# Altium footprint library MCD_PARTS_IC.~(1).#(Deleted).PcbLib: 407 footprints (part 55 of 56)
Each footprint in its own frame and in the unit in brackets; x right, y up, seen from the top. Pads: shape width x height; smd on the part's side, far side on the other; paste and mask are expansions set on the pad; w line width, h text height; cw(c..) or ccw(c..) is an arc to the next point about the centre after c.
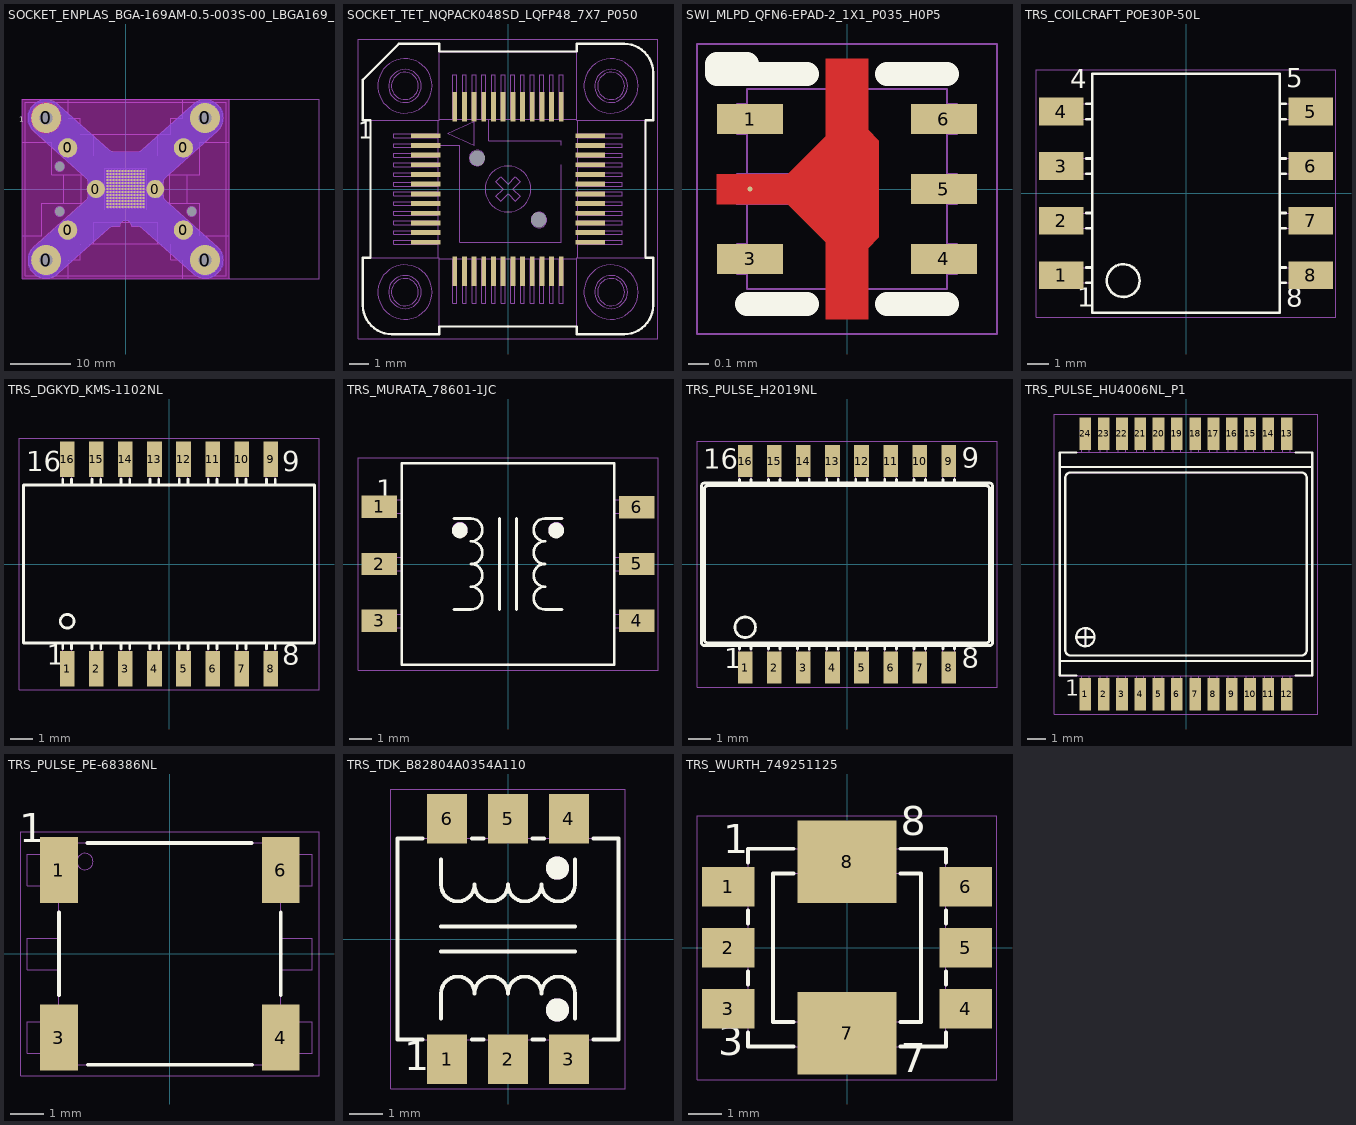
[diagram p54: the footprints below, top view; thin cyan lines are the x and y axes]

## SOCKET_ENPLAS_BGA-169AM-0.5-003S-00_LBGA169_P050_3D-OPEN [mm] "MCD-02114"
height 41
pads (182):
  round 5 hole 2.15 mask+0.05: 0(-13.25,-11.85) 0(-13.25,11.85) 0(13.25,-11.85) 0(13.25,11.85)
  round 0 hole 1.6 unplated mask+0.05: 0(-11,-3.75) 0(-11,3.75) 0(11,-3.75)
  round 3.2 smd paste-2 mask+0.05: 0(-9.65,-6.85) 0(-9.65,6.85) 0(9.65,-6.85) 0(9.65,6.85)
  round 3 smd paste-2 mask+0.05: 0(-4.945,0) 0(4.945,0)
  rrect30% 0.35x0.35 smd paste-0.2 mask+0.05: A1(-3,3) A2(-2.5,3) A3(-2,3) A4(-1.5,3) A5(-1,3) A6(-0.5,3) A7(0,3) A8(0.5,3) A9(1,3) A10(1.5,3) A11(2,3) A12(2.5,3) A13(3,3) B1(-3,2.5) B2(-2.5,2.5) B3(-2,2.5) B4(-1.5,2.5) B5(-1,2.5) B6(-0.5,2.5) B7(0,2.5) B8(0.5,2.5) B9(1,2.5) B10(1.5,2.5) B11(2,2.5) B12(2.5,2.5) B13(3,2.5) C1(-3,2) C2(-2.5,2) C3(-2,2) C4(-1.5,2) C5(-1,2) C6(-0.5,2) C7(0,2) C8(0.5,2) C9(1,2) C10(1.5,2) C11(2,2) C12(2.5,2) C13(3,2) D1(-3,1.5) D2(-2.5,1.5) D3(-2,1.5) D4(-1.5,1.5) D5(-1,1.5) D6(-0.5,1.5) D7(0,1.5) D8(0.5,1.5) D9(1,1.5) D10(1.5,1.5) D11(2,1.5) D12(2.5,1.5) D13(3,1.5) E1(-3,1) E2(-2.5,1) E3(-2,1) E4(-1.5,1) E5(-1,1) E6(-0.5,1) E7(0,1) E8(0.5,1) E9(1,1) E10(1.5,1) E11(2,1) E12(2.5,1) E13(3,1) F1(-3,0.5) F2(-2.5,0.5) F3(-2,0.5) F4(-1.5,0.5) F5(-1,0.5) F6(-0.5,0.5) F7(0,0.5) F8(0.5,0.5) F9(1,0.5) F10(1.5,0.5) F11(2,0.5) F12(2.5,0.5) F13(3,0.5) G1(-3,0) G2(-2.5,0) G3(-2,0) G4(-1.5,0) G5(-1,0) G6(-0.5,0) G7(0,0) G8(0.5,0) G9(1,0) G10(1.5,0) G11(2,0) G12(2.5,0) G13(3,0) H1(-3,-0.5) H2(-2.5,-0.5) H3(-2,-0.5) H4(-1.5,-0.5) H5(-1,-0.5) H6(-0.5,-0.5) H7(0,-0.5) H8(0.5,-0.5) H9(1,-0.5) H10(1.5,-0.5) H11(2,-0.5) H12(2.5,-0.5) H13(3,-0.5) J1(-3,-1) J2(-2.5,-1) J3(-2,-1) J4(-1.5,-1) J5(-1,-1) J6(-0.5,-1) J7(0,-1) J8(0.5,-1) J9(1,-1) J10(1.5,-1) J11(2,-1) J12(2.5,-1) J13(3,-1) K1(-3,-1.5) K2(-2.5,-1.5) K3(-2,-1.5) K4(-1.5,-1.5) K5(-1,-1.5) K6(-0.5,-1.5) K7(0,-1.5) K8(0.5,-1.5) K9(1,-1.5) K10(1.5,-1.5) K11(2,-1.5) K12(2.5,-1.5) K13(3,-1.5) L1(-3,-2) L2(-2.5,-2) L3(-2,-2) L4(-1.5,-2) L5(-1,-2) L6(-0.5,-2) L7(0,-2) L8(0.5,-2) L9(1,-2) L10(1.5,-2) L11(2,-2) L12(2.5,-2) L13(3,-2) M1(-3,-2.5) M2(-2.5,-2.5) M3(-2,-2.5) M4(-1.5,-2.5) M5(-1,-2.5) M6(-0.5,-2.5) M7(0,-2.5) M8(0.5,-2.5) M9(1,-2.5) M10(1.5,-2.5) M11(2,-2.5) M12(2.5,-2.5) M13(3,-2.5) N1(-3,-3) N2(-2.5,-3) N3(-2,-3) N4(-1.5,-3) N5(-1,-3) N6(-0.5,-3) N7(0,-3) N8(0.5,-3) N9(1,-3) N10(1.5,-3) N11(2,-3) N12(2.5,-3) N13(3,-3)
Top Layer:
  circle w0.01: c-13.25,11.85 r1.075
  circle w0.01: c-13.25,11.85 r2.5
Top Layer keep-out:
  region: 4.975,15 4.975,1.5 4.95,1.5 4.803,1.493 4.515,1.435 4.243,1.323 3.998,1.16 3.79,0.952 3.627,0.707 3.515,0.435 3.457,0.147 3.45,0 3.457,-0.147 3.515,-0.435 3.627,-0.707 3.79,-0.952 3.998,-1.16 4.243,-1.323 4.515,-1.435 4.803,-1.493 4.95,-1.5 4.975,-1.5 4.975,-15 0,-15 0,-3.375 3.375,-3.375 3.375,3.375 -3.375,3.375 -3.375,-3.375 0,-3.375 0,-15 -4.95,-15 -4.95,-1.5 -4.803,-1.493 -4.515,-1.435 -4.243,-1.323 -3.998,-1.16 -3.79,-0.952 -3.627,-0.707 -3.515,-0.435 -3.457,-0.147 -3.45,0 -3.457,0.147 -3.515,0.435 -3.627,0.707 -3.79,0.952 -3.998,1.16 -4.243,1.323 -4.515,1.435 -4.803,1.493 -4.95,1.5 -4.95,15
  region: 9.675,15 4.975,15 4.975,1.5 5.122,1.493 5.41,1.435 5.682,1.323 5.927,1.16 6.135,0.952 6.298,0.707 6.41,0.435 6.468,0.147 6.475,0 6.468,-0.147 6.41,-0.435 6.298,-0.707 6.135,-0.952 5.927,-1.16 5.682,-1.323 5.41,-1.435 5.122,-1.493 4.975,-1.5 4.975,-15 9.675,-15 9.675,-8.45 9.518,-8.442 9.211,-8.381 8.921,-8.261 8.66,-8.087 8.438,-7.865 8.264,-7.604 8.144,-7.314 8.083,-7.007 8.075,-6.85 8.083,-6.693 8.144,-6.386 8.264,-6.096 8.438,-5.835 8.66,-5.613 8.921,-5.439 9.211,-5.319 9.518,-5.258 9.675,-5.25 9.675,-4.9 11.025,-4.9 11.025,-4.55 10.947,-4.546 10.793,-4.516 10.648,-4.456 10.517,-4.368 10.407,-4.258 10.319,-4.127 10.259,-3.982 10.229,-3.828 10.225,-3.75 10.229,-3.672 10.259,-3.518 10.319,-3.373 10.407,-3.242 10.517,-3.132 10.648,-3.044 10.793,-2.984 10.947,-2.954 11.025,-2.95 11.025,4.925 9.675,4.925 9.675,5.25 9.518,5.258 9.211,5.319 8.921,5.439 8.66,5.613 8.438,5.835 8.264,6.096 8.144,6.386 8.083,6.693 8.075,6.85 8.083,7.007 8.144,7.314 8.264,7.604 8.438,7.865 8.66,8.087 8.921,8.261 9.211,8.381 9.518,8.442 9.675,8.45
  region: -9.65,15 -4.95,15 -4.95,1.5 -5.097,1.493 -5.385,1.435 -5.657,1.323 -5.902,1.16 -6.11,0.952 -6.273,0.707 -6.385,0.435 -6.443,0.147 -6.45,0 -6.443,-0.147 -6.385,-0.435 -6.273,-0.707 -6.11,-0.952 -5.902,-1.16 -5.657,-1.323 -5.385,-1.435 -5.097,-1.493 -4.95,-1.5 -4.95,-15 -9.65,-15 -9.65,-8.45 -9.493,-8.442 -9.186,-8.381 -8.896,-8.261 -8.635,-8.087 -8.413,-7.865 -8.239,-7.604 -8.119,-7.314 -8.058,-7.007 -8.05,-6.85 -8.058,-6.693 -8.119,-6.386 -8.239,-6.096 -8.413,-5.835 -8.635,-5.613 -8.896,-5.439 -9.186,-5.319 -9.493,-5.258 -9.65,-5.25 -9.65,-4.9 -11,-4.9 -11,-4.55 -10.922,-4.546 -10.768,-4.516 -10.623,-4.456 -10.492,-4.368 -10.382,-4.258 -10.294,-4.127 -10.234,-3.982 -10.204,-3.828 -10.2,-3.75 -10.204,-3.672 -10.234,-3.518 -10.294,-3.373 -10.382,-3.242 -10.492,-3.132 -10.623,-3.044 -10.768,-2.984 -10.922,-2.954 -11,-2.95 -11,2.95 -10.922,2.954 -10.768,2.984 -10.623,3.044 -10.492,3.132 -10.382,3.242 -10.294,3.373 -10.234,3.518 -10.204,3.672 -10.2,3.75 -10.204,3.828 -10.234,3.982 -10.294,4.127 -10.382,4.258 -10.492,4.368 -10.623,4.456 -10.768,4.516 -10.922,4.546 -11,4.55 -11,4.925 -9.65,4.925 -9.65,5.25 -9.493,5.258 -9.186,5.319 -8.896,5.439 -8.635,5.613 -8.413,5.835 -8.239,6.096 -8.119,6.386 -8.058,6.693 -8.05,6.85 -8.058,7.007 -8.119,7.314 -8.239,7.604 -8.413,7.865 -8.635,8.087 -8.896,8.261 -9.186,8.381 -9.493,8.442 -9.65,8.45
  region: -17.25,15 -13.25,15 -13.25,14.347 -13.253,14.347 -13.498,14.335 -13.978,14.239 -14.43,14.052 -14.837,13.78 -15.183,13.434 -15.455,13.027 -15.642,12.575 -15.738,12.095 -15.75,11.85 -15.738,11.605 -15.642,11.125 -15.455,10.673 -15.183,10.266 -14.837,9.92 -14.43,9.648 -13.978,9.461 -13.498,9.365 -13.253,9.353 -13.25,9.353 -13.25,-9.353 -13.253,-9.353 -13.498,-9.365 -13.978,-9.461 -14.43,-9.648 -14.837,-9.92 -15.183,-10.266 -15.455,-10.673 -15.642,-11.125 -15.738,-11.605 -15.75,-11.85 -15.738,-12.095 -15.642,-12.575 -15.455,-13.027 -15.183,-13.434 -14.837,-13.78 -14.43,-14.052 -13.978,-14.239 -13.498,-14.335 -13.253,-14.347 -13.25,-14.347 -13.25,-15 -17.25,-15
  region: 17.275,15 13.275,15 13.275,14.347 13.278,14.347 13.523,14.335 14.003,14.239 14.455,14.052 14.862,13.78 15.208,13.434 15.48,13.027 15.667,12.575 15.763,12.095 15.775,11.85 15.763,11.605 15.667,11.125 15.48,10.673 15.208,10.266 14.862,9.92 14.455,9.648 14.003,9.461 13.523,9.365 13.278,9.353 13.275,9.353 13.275,-9.353 13.278,-9.353 13.523,-9.365 14.003,-9.461 14.455,-9.648 14.862,-9.92 15.208,-10.266 15.48,-10.673 15.667,-11.125 15.763,-11.605 15.775,-11.85 15.763,-12.095 15.667,-12.575 15.48,-13.027 15.208,-13.434 14.862,-13.78 14.455,-14.052 14.003,-14.239 13.523,-14.335 13.278,-14.347 13.275,-14.347 13.275,-15 17.275,-15
  region: -13.25,15 -9.65,15 -9.65,8.45 -9.807,8.442 -10.114,8.381 -10.404,8.261 -10.665,8.087 -10.887,7.865 -11.061,7.604 -11.181,7.314 -11.242,7.007 -11.25,6.85 -11.242,6.693 -11.181,6.386 -11.061,6.096 -10.887,5.835 -10.665,5.613 -10.404,5.439 -10.114,5.319 -9.807,5.258 -9.65,5.25 -9.65,4.925 -11,4.925 -11,4.55 -11.078,4.546 -11.232,4.516 -11.377,4.456 -11.508,4.368 -11.618,4.258 -11.706,4.127 -11.766,3.982 -11.796,3.828 -11.8,3.75 -11.796,3.672 -11.766,3.518 -11.706,3.373 -11.618,3.242 -11.508,3.132 -11.377,3.044 -11.232,2.984 -11.078,2.954 -11,2.95 -11,-2.95 -11.078,-2.954 -11.232,-2.984 -11.377,-3.044 -11.508,-3.132 -11.618,-3.242 -11.706,-3.373 -11.766,-3.518 -11.796,-3.672 -11.8,-3.75 -11.796,-3.828 -11.766,-3.982 -11.706,-4.127 -11.618,-4.258 -11.508,-4.368 -11.377,-4.456 -11.232,-4.516 -11.078,-4.546 -11,-4.55 -11,-4.9 -9.65,-4.9 -9.65,-5.25 -9.807,-5.258 -10.114,-5.319 -10.404,-5.439 -10.665,-5.613 -10.887,-5.835 -11.061,-6.096 -11.181,-6.386 -11.242,-6.693 -11.25,-6.85 -11.242,-7.007 -11.181,-7.314 -11.061,-7.604 -10.887,-7.865 -10.665,-8.087 -10.404,-8.261 -10.114,-8.381 -9.807,-8.442 -9.65,-8.45 -9.65,-15 -13.25,-15 -13.25,-14.347 -13.247,-14.347 -13.002,-14.335 -12.522,-14.239 -12.07,-14.052 -11.663,-13.78 -11.317,-13.434 -11.045,-13.027 -10.858,-12.575 -10.762,-12.095 -10.75,-11.85 -10.762,-11.605 -10.858,-11.125 -11.045,-10.673 -11.317,-10.266 -11.663,-9.92 -12.07,-9.648 -12.522,-9.461 -13.002,-9.365 -13.247,-9.353 -13.25,-9.353 -13.25,9.353 -13.247,9.353 -13.002,9.365 -12.522,9.461 -12.07,9.648 -11.663,9.92 -11.317,10.266 -11.045,10.673 -10.857,11.125 -10.762,11.605 -10.75,11.85 -10.762,12.095 -10.857,12.575 -11.045,13.027 -11.317,13.434 -11.663,13.78 -12.07,14.052 -12.522,14.239 -13.002,14.335 -13.247,14.347 -13.253,14.347
  region: 13.275,15 9.675,15 9.675,8.45 9.832,8.442 10.139,8.381 10.429,8.261 10.69,8.087 10.912,7.865 11.086,7.604 11.206,7.314 11.267,7.007 11.275,6.85 11.267,6.693 11.206,6.386 11.086,6.096 10.912,5.835 10.69,5.613 10.429,5.439 10.139,5.319 9.832,5.258 9.675,5.25 9.675,4.925 11.025,4.925 11.025,-2.95 11.103,-2.954 11.257,-2.984 11.402,-3.044 11.532,-3.132 11.643,-3.242 11.731,-3.373 11.791,-3.518 11.821,-3.672 11.825,-3.75 11.821,-3.828 11.791,-3.982 11.731,-4.127 11.643,-4.258 11.533,-4.368 11.402,-4.456 11.257,-4.516 11.103,-4.546 11.025,-4.55 11.025,-4.9 9.675,-4.9 9.675,-5.25 9.832,-5.258 10.139,-5.319 10.429,-5.439 10.69,-5.613 10.912,-5.835 11.086,-6.096 11.206,-6.386 11.267,-6.693 11.275,-6.85 11.267,-7.007 11.206,-7.314 11.086,-7.604 10.912,-7.865 10.69,-8.087 10.429,-8.261 10.139,-8.381 9.832,-8.442 9.675,-8.45 9.675,-15 13.275,-15 13.275,-14.347 13.03,-14.335 12.55,-14.24 12.097,-14.053 11.69,-13.781 11.343,-13.435 11.071,-13.028 10.883,-12.575 10.787,-12.095 10.775,-11.85 10.787,-11.605 10.883,-11.125 11.07,-10.673 11.342,-10.266 11.688,-9.92 12.095,-9.648 12.547,-9.461 13.027,-9.365 13.272,-9.353 13.275,9.353 13.03,9.365 12.55,9.46 12.097,9.647 11.69,9.919 11.343,10.265 11.071,10.672 10.883,11.125 10.787,11.605 10.775,11.85 10.787,12.095 10.882,12.575 11.07,13.027 11.342,13.434 11.688,13.78 12.095,14.052 12.547,14.239 13.027,14.335 13.272,14.347
Bottom Layer keep-out:
  region: 1,-6.247 2.238,-6.25 2.113,-6.1 0.997,-6.198
  region: 194 vertices and 0 holes, not listed, extent -16.275,-14.875 16.263,14.875
Top Overlay:
  text "1" at -17.775,10.85 h1.5
Bottom Overlay:
  lines w0.1: 6.542,-1.832 15.371,-9.729 cw(c13.25,-11.85) 11.129,-13.971 2.781,-6.506 ccw(c2.113,-7.25) 2.125,-6.25 1,-6.25 ccw(c0,-6.25) -1,-6.25 -2.125,-6.25 ccw(c-2.113,-7.25) -2.781,-6.506 -11.129,-13.971 cw(c-13.25,-11.85) -15.371,-9.729 -6.625,-1.906 ccw(c-7.25,-1.125) -6.25,-1.125 -6.25,1.125 ccw(c-7.25,1.125) -6.625,1.906 -15.371,9.729 cw(c-13.25,11.85) -11.129,13.971 -2.781,6.506 ccw(c-2.113,7.25) -2.125,6.25 2.125,6.25 ccw(c2.113,7.25) 2.781,6.506 11.129,13.971 cw(c13.25,11.85) 15.371,9.729 6.625,1.906 ccw(c7.25,1.125) 6.25,1.125 6.25,-1.125 ccw(c7.25,-1.125) 6.625,-1.906
Top Solder:
  rectangle: -17.25,-15 17.25,15
M14-Top Assembly:
  drawing of 1377 lines, arcs and shapes, not listed
  text "'.Designator'" at -2,3.5 h0.75
  text "A1" at -3.375,3.621 h0.8
  text "A13" at 2.375,3.621 h0.8
  text "N1" at -3.375,-4.104 h0.8
  text "N13" at 2.4,-4.129 h0.8
M15-Bottom Assembly:
  circle w0.01: c-13.25,11.85 r1.075
  circle w0.01: c-13.25,11.85 r2.5
  circle w0.01: c-13.25,-11.85 r1.075
  circle w0.01: c-13.25,-11.85 r2.5
  circle w0.01: c13.25,-11.85 r1.075
  circle w0.01: c13.25,-11.85 r2.5
  circle w0.01: c13.25,11.85 r1.075
  circle w0.01: c13.25,11.85 r2.5
  lines w0.01: 6.542,-1.832 15.371,-9.729 cw(c13.25,-11.85) 11.129,-13.971 2.781,-6.506 ccw(c2.113,-7.25) 2.125,-6.25 1,-6.25 ccw(c0,-6.25) -1,-6.25 -2.125,-6.25 ccw(c-2.113,-7.25) -2.781,-6.506 -11.129,-13.971 cw(c-13.25,-11.85) -15.371,-9.729 -6.625,-1.906 ccw(c-7.25,-1.125) -6.25,-1.125 -6.25,1.125 ccw(c-7.25,1.125) -6.625,1.906 -15.371,9.729 cw(c-13.25,11.85) -11.129,13.971 -2.781,6.506 ccw(c-2.113,7.25) -2.125,6.25 2.125,6.25 ccw(c2.113,7.25) 2.781,6.506 11.129,13.971 cw(c13.25,11.85) 15.371,9.729 6.625,1.906 ccw(c7.25,1.125) 6.25,1.125 6.25,-1.125 ccw(c7.25,-1.125) 6.625,-1.906
M16-Top Courtyard:
  lines w0.01: -10.3,-2.4 -10.3,2.4 ; -5.33,-9.1 -5.33,-5.51 5.33,-5.51 5.33,-9.1 ; -5.33,9.1 -5.33,5.51 5.33,5.51 5.33,9.1 ; 10.3,-2.4 10.3,2.4 ; -9.55,11.8 -9.55,15 ; -9.55,11.8 -9.55,15 ; -9.55,11.8 -7.55,11.8 -7.55,9.1 7.55,9.1 7.55,11.8 9.55,11.8 9.55,15 -9.55,15 ; 17.25,15 32.25,15 32.25,-15 ; 17.25,15 17.25,-15 32.25,-15 ; 17.25,15 -17.25,15 -17.25,-15 32.25,-15 ; -17.25,-7.8 -13.95,-7.8 -13.95,-2.4 -7.39,-2.4 -7.39,2.4 -12.35,2.4 -12.35,7.8 -17.25,7.8 -17.25,-7.8 ; -9.55,-15 9.55,-15 9.55,-11.8 7.55,-11.8 7.55,-9.1 -7.55,-9.1 -7.55,-11.8 -9.55,-11.8 -9.55,-15 ; 7.39,-2.4 7.39,2.4 12.35,2.4 12.35,7.8 17.25,7.8 17.25,-7.8 12.35,-7.8 12.35,-2.4 7.39,-2.4
  text "COVER KEEP OUT AREA" at 23.714,-10.75 h2
  text "(MAX HEIGHT 3.5MM)" at 27.08,-9.25 h2
  text "ZONE." at 10.112,-0.938 h0.7
  text "RESTRICTION" at 9.424,-2.063 h0.7
  text "COMP HEIGHT" at 8.812,-2.312 h0.7
  text "2.0MM MAX" at 8.083,-1.75 h0.7
  text "HEIGHT RESTRICTION ZONE." at 15.714,-6.39 h1
  text "2.5MM MAXIMUM COMPONENT" at 14.444,-6.75 h1
  text "2.5MM MAXIMUM COMPONENT" at 6.75,11.529 h1
  text "HEIGHT RESTRICTION ZONE." at 6.39,12.799 h1
  text "2.0MM MAXIMUM" at 3.75,6.646 h1
  text "COMPONENT HEIGHT" at 4.75,7.654 h1
  text "RESTRICTION ZONE." at 4.64,8.674 h1
  text "RESTRICTION ZONE." at -4.64,-8.674 h1
  text "COMPONENT HEIGHT" at -4.75,-7.654 h1
  text "2.0MM MAXIMUM" at -3.75,-6.646 h1
  text "HEIGHT RESTRICTION ZONE." at -6.39,-12.799 h1
  text "2.5MM MAXIMUM COMPONENT" at -6.75,-11.529 h1
  text "2.5MM MAXIMUM COMPONENT" at -15.154,6.75 h1
  text "HEIGHT RESTRICTION ZONE." at -16.424,6.39 h1
  text "2.0MM MAX" at -8.083,1.75 h0.7
  text "COMP HEIGHT" at -8.812,2.312 h0.7
  text "RESTRICTION" at -9.424,2.063 h0.7
  text "ZONE." at -10.111,0.938 h0.7
M17-Bottom Courtyard:
  lines w0.01: 6.542,-1.832 15.371,-9.729 cw(c13.25,-11.85) 11.129,-13.971 2.781,-6.506 ccw(c2.113,-7.25) 2.125,-6.25 1,-6.25 ccw(c0,-6.25) -1,-6.25 -2.125,-6.25 ccw(c-2.113,-7.25) -2.781,-6.506 -11.129,-13.971 cw(c-13.25,-11.85) -15.371,-9.729 -6.625,-1.906 ccw(c-7.25,-1.125) -6.25,-1.125 -6.25,1.125 ccw(c-7.25,1.125) -6.625,1.906 -15.371,9.729 cw(c-13.25,11.85) -11.129,13.971 -2.781,6.506 ccw(c-2.113,7.25) -2.125,6.25 2.125,6.25 ccw(c2.113,7.25) 2.781,6.506 11.129,13.971 cw(c13.25,11.85) 15.371,9.729 6.625,1.906 ccw(c7.25,1.125) 6.25,1.125 6.25,-1.125 ccw(c7.25,-1.125) 6.625,-1.906
3D body: height 4.4, standoff -3.6, extent 12.184,-12.923 14.325,-10.777
3D body: height 3, standoff 2, extent 10.75,-14.347 15.75,-9.353
3D body: height 4, standoff 3, extent 10.75,-11.6 13,-9.35
3D body: height 4, standoff 3, extent 13.5,-11.6 15.75,-9.35
3D body: height 4, standoff 3, extent 10.75,-14.35 13,-12.1
3D body: height 4, standoff 3, extent 13.5,-14.35 15.75,-12.1
3D body: height 4.4, standoff -3.6, extent 12.184,10.777 14.325,12.923
3D body: height 3, standoff 2, extent 10.75,9.353 15.75,14.347
3D body: height 4, standoff 3, extent 10.75,12.1 13,14.35
3D body: height 4, standoff 3, extent 13.5,12.1 15.75,14.35
3D body: height 4, standoff 3, extent 10.75,9.35 13,11.6
3D body: height 4, standoff 3, extent 13.5,9.35 15.75,11.6
3D body: height 4.4, standoff -3.6, extent -14.316,10.777 -12.175,12.923
3D body: height 3, standoff 2, extent -15.75,9.353 -10.75,14.347
3D body: height 4, standoff 3, extent -15.75,12.1 -13.5,14.35
3D body: height 4, standoff 3, extent -13,12.1 -10.75,14.35
3D body: height 4, standoff 3, extent -15.75,9.35 -13.5,11.6
3D body: height 4, standoff 3, extent -13,9.35 -10.75,11.6
3D body: height 4.4, standoff -3.6, extent -14.316,-12.923 -12.175,-10.777
3D body: height 3, standoff 2, extent -15.75,-14.347 -10.75,-9.353
3D body: height 4, standoff 3, extent -15.75,-11.6 -13.5,-9.35
3D body: height 4, standoff 3, extent -13,-11.6 -10.75,-9.35
3D body: height 4, standoff 3, extent -15.75,-14.35 -13.5,-12.1
3D body: height 4, standoff 3, extent -13,-14.35 -10.75,-12.1
3D body: height -1.6, standoff -3.6, extent -16.25,-14.875 16.262,14.875
3D body: height 41, standoff 0, extent -16.75,-14.5 16.75,14.5
3D body "5C-042-342-01_IC_SOCKET_Open_with_PCB.STEP": height 41.05, standoff -5.83, extent -17.25,-15 32.252,15

## SOCKET_TET_NQPACK048SD_LQFP48_7X7_P050 [mm] "MCD-03917"
height 9.45
pads (50):
  round 0 hole 0.8 unplated mask+0.05: 0(-1.6,1.6) 0(1.6,-1.6)
  rect 1.5x0.25 smd mask+0.05: 1(-4.25,2.75) 2(-4.25,2.25) 3(-4.25,1.75) 4(-4.25,1.25) 5(-4.25,0.75) 6(-4.25,0.25) 7(-4.25,-0.25) 8(-4.25,-0.75) 9(-4.25,-1.25) 10(-4.25,-1.75) 11(-4.25,-2.25) 12(-4.25,-2.75) 25(4.25,-2.75) 26(4.25,-2.25) 27(4.25,-1.75) 28(4.25,-1.25) 29(4.25,-0.75) 30(4.25,-0.25) 31(4.25,0.25) 32(4.25,0.75) 33(4.25,1.25) 34(4.25,1.75) 35(4.25,2.25) 36(4.25,2.75)
  rect 0.25x1.5 smd mask+0.05: 13(-2.75,-4.25) 14(-2.25,-4.25) 15(-1.75,-4.25) 16(-1.25,-4.25) 17(-0.75,-4.25) 18(-0.25,-4.25) 19(0.25,-4.25) 20(0.75,-4.25) 21(1.25,-4.25) 22(1.75,-4.25) 23(2.25,-4.25) 24(2.75,-4.25) 37(2.75,4.25) 38(2.25,4.25) 39(1.75,4.25) 40(1.25,4.25) 41(0.75,4.25) 42(0.25,4.25) 43(-0.25,4.25) 44(-0.75,4.25) 45(-1.25,4.25) 46(-1.75,4.25) 47(-2.25,4.25) 48(-2.75,4.25)
Top Overlay:
  lines w0.12: -7.5,-6 ccw(c-6,-6) -6,-7.5 -3.55,-7.5 -3.55,-7.1 3.55,-7.1 3.55,-7.5 6,-7.5 ccw(c6,-6) 7.5,-6 7.5,-3.55 7.1,-3.55 7.1,3.55 7.5,3.55 7.5,6 ccw(c6,6) 6,7.5 3.55,7.5 3.55,7.1 -3.55,7.1 -3.55,7.5 -5.638,7.5 -7.5,5.638 -7.5,3.55 -7.1,3.55 -7.1,-3.55 -7.5,-3.55 -7.5,-6
  text "1" at -7.75,2.297 h1.5
M14-Top Assembly:
  drawing of 221 lines, arcs and shapes, not listed
  text "048SD" at -2.05,-2.389 h1
  text "TET" at 0.85,1.475 h1
  text "1" at -6.55,2.325 h1.5
  text "'.Designator'" at -2,-0.5 h0.75
M16-Top Courtyard:
  lines w0.025: -7.75,-7.75 -7.75,7.75 7.75,7.75 7.75,-7.75 -7.75,-7.75
3D body: height 5.55, standoff 0, extent -5,-5 5,5
3D body: height 9.45, standoff 5.55, extent -7.5,3.55 -3.55,7.5
3D body: height 9.45, standoff 5.55, extent -7.5,-7.5 -3.55,-3.55
3D body: height 9.45, standoff 5.55, extent 3.55,-7.5 7.5,-3.55
3D body: height 9.45, standoff 5.55, extent 3.55,3.55 7.5,7.5
3D body: height 7, standoff 5.55, extent -7.1,-7.1 7.1,7.1

## SWI_MLPD_QFN6-EPAD-2_1X1_P035_H0P5 [mm] "MCD-03674"
height 0.5
pads (6):
  rect 0.33x0.15 smd mask+0.05: 1(-0.485,0.35) 3(-0.485,-0.35) 4(0.485,-0.35) 5(0.485,0) 6(0.485,0.35)
  round 0.025 smd mask+0.012: 2(-0.485,0)
Top Layer:
  region: -0.295,0.075 -0.105,0.265 -0.105,0.65 0.105,0.65 0.105,0.295 0.16,0.24 0.16,-0.24 0.105,-0.295 0.105,-0.65 -0.105,-0.65 -0.105,-0.265 -0.295,-0.075 -0.65,-0.075 -0.65,0.075
Top Overlay:
  lines w0.12: -0.5,-0.575 -0.2,-0.575 ; -0.2,0.575 -0.5,0.575 ; 0.2,-0.575 0.5,-0.575 ; 0.2,0.575 0.5,0.575 ; -0.5,0.575 -0.5,0.625 -0.65,0.625 -0.65,0.575 -0.5,0.575
Top Solder:
  rectangle: -0.7,-0.125 -0.23,0.125
M14-Top Assembly:
  lines w0.01: -0.5,-0.425 -0.55,-0.425 -0.55,-0.275 -0.5,-0.275 ; -0.5,-0.075 -0.55,-0.075 ; -0.5,0.275 -0.55,0.275 -0.55,0.425 -0.5,0.425 ; 0.5,-0.425 0.55,-0.425 0.55,-0.275 0.5,-0.275 ; 0.5,-0.075 0.55,-0.075 0.55,0.075 0.5,0.075 ; 0.5,0.275 0.55,0.275 0.55,0.425 0.5,0.425 ; -0.55,-0.075 -0.55,0.075 -0.25,0.075 -0.075,0.25 -0.075,0.55 0.075,0.55 0.075,0.275 0.13,0.22 ; -0.55,-0.075 -0.25,-0.075 -0.075,-0.25 -0.075,-0.55 0.075,-0.55 0.075,-0.275 0.13,-0.22 ; 0.13,-0.22 0.13,0.22 ; 0.13,-0.22 0.13,-0.22 ; 0.13,0.22 0.13,0.22 ; 0.13,0.22 0.13,0.22 ; -0.5,-0.5 0.5,-0.5 0.5,0.5 -0.5,0.5 -0.5,-0.5
  text "'.Designator'" at -2,-0.5 h0.75
  text "1" at -0.626,0.288 h0.2
  text "3" at -0.663,-0.411 h0.2
  text "4" at 0.57,-0.414 h0.2
  text "6" at 0.57,0.287 h0.2
  text "2" at -0.043,-0.064 h0.2
M16-Top Courtyard:
  lines w0.01: -0.75,-0.725 0.75,-0.725 0.75,0.725 -0.1,0.725 -0.75,0.725 -0.75,-0.725
3D body: height 0.51, standoff 0.5, extent -0.45,0.25 -0.25,0.45
3D body: height 0.5, standoff 0.05, extent -0.5,-0.5 0.5,0.5
3D body: height 0.18, standoff 0, extent -0.55,-0.425 -0.5,-0.275
3D body: height 0.18, standoff 0, extent -0.55,-0.075 -0.5,0.075
3D body: height 0.18, standoff 0, extent -0.55,0.275 -0.5,0.425
3D body: height 0.05, standoff 0, extent -0.5,-0.5 0.13,0.5
3D body: height 0.18, standoff 0, extent -0.075,-0.55 0.075,-0.5
3D body: height 0.18, standoff 0, extent 0.5,0.275 0.55,0.425
3D body: height 0.18, standoff 0, extent 0.5,-0.075 0.55,0.075
3D body: height 0.18, standoff 0, extent 0.5,-0.425 0.55,-0.275
3D body: height 0.18, standoff 0, extent -0.075,0.5 0.075,0.55
3D body: height 0.05, standoff 0, extent 0.325,0.275 0.55,0.425
3D body: height 0.05, standoff 0, extent 0.325,-0.075 0.55,0.075
3D body: height 0.05, standoff 0, extent 0.325,-0.425 0.55,-0.275
3D body: height 0.05, standoff 0, extent -0.55,-0.425 -0.325,-0.275
3D body: height 0.05, standoff 0, extent -0.55,0.275 -0.325,0.425

## TRS_COILCRAFT_POE30P-50L [mm]
height 9.02
pads (8):
  rect 2.03x1.27 smd mask+0.05: 1(-5.715,-3.75) 2(-5.715,-1.25) 3(-5.715,1.25) 4(-5.715,3.75) 5(5.715,3.75) 6(5.715,1.25) 7(5.715,-1.25) 8(5.715,-3.75)
Top Overlay:
  circle w0.12: c-2.875,-4 r0.752
  lines w0.12: -4.575,-4.1 -4.3,-4.1 ; -4.575,-3.4 -4.3,-3.4 ; -4.575,-1.6 -4.3,-1.6 ; -4.575,-0.9 -4.3,-0.9 ; -4.575,0.9 -4.3,0.9 ; -4.575,1.6 -4.3,1.6 ; -4.575,3.4 -4.3,3.4 ; -4.575,4.1 -4.3,4.1 ; -4.3,5.45 -4.275,5.475 4.3,5.475 4.3,-5.475 -3.375,-5.475 -4.3,-5.475 -4.3,5.475 ; 4.3,-4.1 4.575,-4.1 ; 4.3,-3.4 4.575,-3.4 ; 4.3,-1.6 4.575,-1.6 ; 4.3,-0.9 4.575,-0.9 ; 4.3,0.9 4.575,0.9 ; 4.3,1.6 4.575,1.6 ; 4.3,3.4 4.575,3.4 ; 4.3,4.1 4.575,4.1
  text "8" at 4.6,-5.5 h1.5
  text "5" at 4.6,4.575 h1.5
  text "4" at -5.3,4.525 h1.5
  text "1" at -4.975,-5.5 h1.5
M14-Top Assembly:
  circle w0.01: c-2.875,-4 r0.75
  lines w0.01: -4.3,-4.1 -6.6,-4.1 -6.6,-3.4 -4.3,-3.4 ; -4.3,-1.6 -6.6,-1.6 -6.6,-0.9 -4.3,-0.9 ; -4.3,0.9 -6.6,0.9 -6.6,1.6 -4.3,1.6 ; -4.3,3.4 -6.6,3.4 -6.6,4.1 -4.3,4.1 ; 4.3,-4.1 6.6,-4.1 6.6,-3.4 4.3,-3.4 ; 4.3,-1.6 6.6,-1.6 6.6,-0.9 4.3,-0.9 ; 4.3,0.9 6.6,0.9 6.6,1.6 4.3,1.6 ; 4.3,3.4 6.6,3.4 6.6,4.1 4.3,4.1 ; -4.3,-5.46 4.3,-5.46 4.3,5.46 -4.3,5.46 -4.3,-5.46
  text "8" at 5.5,-4.1 h1.1
  text "7" at 5.5,-1.6 h1.1
  text "6" at 5.5,0.9 h1.1
  text "5" at 5.475,3.4 h1.1
  text "4" at -5.975,3.4 h1.1
  text "3" at -5.975,0.9 h1.1
  text "2" at -5.95,-1.6 h1.1
  text "1" at -5.825,-4.1 h1.1
  text "'.Designator'" at -2,-0.5 h0.75
M16-Top Courtyard:
  lines w0.01: -6.875,-5.675 -6.875,4.225 -6.875,5.675 6.875,5.675 6.875,-5.675 -6.875,-5.675
3D body "POE30P-50L.STEP": height 9.02, standoff 0, extent -6.6,-5.46 6.6,5.46
3D body: height 9.02, standoff 0, extent -4.3,-5.45 4.3,5.45

## TRS_DGKYD_KMS-1102NL [mm]
height 6.2
pads (16):
  rect 0.64x1.55 smd mask+0.05: 1(-4.445,-4.575) 2(-3.175,-4.575) 3(-1.905,-4.575) 4(-0.635,-4.575) 5(0.635,-4.575) 6(1.905,-4.575) 7(3.175,-4.575) 8(4.445,-4.575) 9(4.445,4.575) 10(3.175,4.575) 11(1.905,4.575) 12(0.635,4.575) 13(-0.635,4.575) 14(-1.905,4.575) 15(-3.175,4.575) 16(-4.445,4.575)
Top Overlay:
  circle w0.12: c-4.445,-2.5 r0.3
  lines w0.12: -4.635,-3.7 -4.635,-3.45 ; -4.635,3.45 -4.635,3.7 ; -4.255,-3.7 -4.255,-3.45 ; -4.255,3.45 -4.255,3.7 ; -3.365,-3.7 -3.365,-3.45 ; -3.365,3.45 -3.365,3.7 ; -2.984,-3.7 -2.984,-3.45 ; -2.984,3.45 -2.984,3.7 ; -2.095,-3.7 -2.095,-3.45 ; -2.095,3.45 -2.095,3.7 ; -1.714,-3.7 -1.714,-3.45 ; -1.714,3.45 -1.714,3.7 ; -0.826,-3.7 -0.826,-3.45 ; -0.826,3.45 -0.826,3.7 ; -0.445,-3.7 -0.445,-3.45 ; -0.445,3.45 -0.445,3.7 ; 0.445,-3.7 0.445,-3.45 ; 0.445,3.45 0.445,3.7 ; 0.826,-3.7 0.826,-3.45 ; 0.826,3.45 0.826,3.7 ; 1.714,-3.7 1.714,-3.45 ; 1.714,3.45 1.714,3.7 ; 2.095,-3.7 2.095,-3.45 ; 2.095,3.45 2.095,3.7 ; 2.984,-3.7 2.984,-3.45 ; 2.984,3.45 2.984,3.7 ; 3.365,-3.7 3.365,-3.45 ; 3.365,3.45 3.365,3.7 ; 4.255,-3.7 4.255,-3.45 ; 4.255,3.45 4.255,3.7 ; 4.635,-3.7 4.635,-3.45 ; 4.635,3.45 4.635,3.7 ; -6.35,-3.45 6.35,-3.45 6.35,3.45 -6.35,3.45 -6.35,-3.45
  text "16" at -6.223,3.75 h1.5
  text "9" at 4.953,3.75 h1.5
  text "8" at 4.953,-4.7 h1.5
  text "1" at -5.334,-4.7 h1.5
M14-Top Assembly:
  lines w0.01: -4.635,-4 -4.255,-4 ; -4.635,-3.45 -4.635,-4.7 -4.255,-4.7 -4.255,-3.45 ; -4.635,3.45 -4.635,4.7 -4.255,4.7 -4.255,3.45 ; -4.635,4 -4.255,4 ; -3.365,-4 -2.984,-4 ; -3.365,-3.45 -3.365,-4.7 -2.984,-4.7 -2.984,-3.45 ; -3.365,3.45 -3.365,4.7 -2.984,4.7 -2.984,3.45 ; -3.365,4 -2.984,4 ; -2.095,-4 -1.714,-4 ; -2.095,-3.45 -2.095,-4.7 -1.714,-4.7 -1.714,-3.45 ; -2.095,3.45 -2.095,4.7 -1.714,4.7 -1.714,3.45 ; -2.095,4 -1.714,4 ; -0.826,-4 -0.445,-4 ; -0.826,-3.45 -0.826,-4.7 -0.445,-4.7 -0.445,-3.45 ; -0.826,3.45 -0.826,4.7 -0.445,4.7 -0.445,3.45 ; -0.826,4 -0.445,4 ; 0.445,-4 0.826,-4 ; 0.445,-3.45 0.445,-4.7 0.826,-4.7 0.826,-3.45 ; 0.445,3.45 0.445,4.7 0.826,4.7 0.826,3.45 ; 0.445,4 0.826,4 ; 1.714,-4 2.095,-4 ; 1.714,-3.45 1.714,-4.7 2.095,-4.7 2.095,-3.45 ; 1.714,3.45 1.714,4.7 2.095,4.7 2.095,3.45 ; 1.714,4 2.095,4 ; 2.984,-4 3.365,-4 ; 2.984,-3.45 2.984,-4.7 3.365,-4.7 3.365,-3.45 ; 2.984,3.45 2.984,4.7 3.365,4.7 3.365,3.45 ; 2.984,4 3.365,4 ; 4.255,-4 4.635,-4 ; 4.255,-3.45 4.255,-4.7 4.635,-4.7 4.635,-3.45 ; 4.255,3.45 4.255,4.7 4.635,4.7 4.635,3.45 ; 4.255,4 4.635,4 ; -6.35,-3.45 -6.35,3.45 6.35,3.45 6.35,-3.45 -6.35,-3.45
  text "'.Designator'" at -2,-0.5 h0.75
  text "1" at -4.635,-3.35 h1.5
  text "8" at 4.127,-3.35 h1.5
  text "9" at 4.127,2.4 h1.5
  text "16" at -5.08,2.4 h1.5
M16-Top Courtyard:
  lines w0.01: -6.55,-5.5 6.5,-5.5 6.55,-5.5 6.55,5.5 -6.55,5.5 -6.55,3.45 -6.55,-5.5
3D body: height 1.2, standoff 1, extent 4.255,-4.25 4.635,-3.45
3D body: height 1, standoff 0, extent 4.255,-4.25 4.635,-4
3D body: height 0.2, standoff 0, extent 4.255,-4.7 4.635,-4
3D body: height 1.2, standoff 1, extent 2.984,-4.25 3.365,-3.45
3D body: height 1, standoff 0, extent 2.984,-4.25 3.365,-4
3D body: height 0.2, standoff 0, extent 2.984,-4.7 3.365,-4
3D body: height 1.2, standoff 1, extent 1.714,-4.25 2.095,-3.45
3D body: height 1, standoff 0, extent 1.714,-4.25 2.095,-4
3D body: height 0.2, standoff 0, extent 1.714,-4.7 2.095,-4
3D body: height 1.2, standoff 1, extent 0.445,-4.25 0.826,-3.45
3D body: height 1, standoff 0, extent 0.445,-4.25 0.826,-4
3D body: height 0.2, standoff 0, extent 0.445,-4.7 0.826,-4
3D body: height 1.2, standoff 1, extent -0.826,-4.25 -0.445,-3.45
3D body: height 1, standoff 0, extent -0.826,-4.25 -0.445,-4
3D body: height 0.2, standoff 0, extent -0.826,-4.7 -0.445,-4
3D body: height 1.2, standoff 1, extent -2.095,-4.25 -1.714,-3.45
3D body: height 1, standoff 0, extent -2.095,-4.25 -1.714,-4
3D body: height 0.2, standoff 0, extent -2.095,-4.7 -1.714,-4
3D body: height 1.2, standoff 1, extent -3.365,-4.25 -2.984,-3.45
3D body: height 1, standoff 0, extent -3.365,-4.25 -2.984,-4
3D body: height 0.2, standoff 0, extent -3.365,-4.7 -2.984,-4
3D body: height 1.2, standoff 1, extent -4.635,-4.25 -4.255,-3.45
3D body: height 1, standoff 0, extent -4.635,-4.25 -4.255,-4
3D body: height 0.2, standoff 0, extent -4.635,-4.7 -4.255,-4
3D body: height 1.2, standoff 1, extent 4.255,3.45 4.635,4.25
3D body: height 1, standoff 0, extent 4.255,4 4.635,4.25
3D body: height 0.2, standoff 0, extent 4.255,4 4.635,4.7
3D body: height 1.2, standoff 1, extent 2.984,3.45 3.365,4.25
3D body: height 1, standoff 0, extent 2.984,4 3.365,4.25
3D body: height 0.2, standoff 0, extent 2.984,4 3.365,4.7
3D body: height 1.2, standoff 1, extent 1.714,3.45 2.095,4.25
3D body: height 1, standoff 0, extent 1.714,4 2.095,4.25
3D body: height 0.2, standoff 0, extent 1.714,4 2.095,4.7
3D body: height 1.2, standoff 1, extent 0.445,3.45 0.826,4.25
3D body: height 1, standoff 0, extent 0.445,4 0.826,4.25
3D body: height 0.2, standoff 0, extent 0.445,4 0.826,4.7
3D body: height 1.2, standoff 1, extent -0.826,3.45 -0.445,4.25
3D body: height 1, standoff 0, extent -0.826,4 -0.445,4.25
3D body: height 0.2, standoff 0, extent -0.826,4 -0.445,4.7
3D body: height 1.2, standoff 1, extent -2.095,3.45 -1.714,4.25
3D body: height 1, standoff 0, extent -2.095,4 -1.714,4.25
3D body: height 0.2, standoff 0, extent -2.095,4 -1.714,4.7
3D body: height 1.2, standoff 1, extent -3.365,3.45 -2.984,4.25
3D body: height 1, standoff 0, extent -3.365,4 -2.984,4.25
3D body: height 0.2, standoff 0, extent -3.365,4 -2.984,4.7
3D body: height 6.3, standoff 6.2, extent -4.742,-2.799 -4.145,-2.2
3D body: height 0.2, standoff 0, extent -4.635,4 -4.255,4.7
3D body: height 1, standoff 0, extent -4.635,4 -4.255,4.25
3D body: height 1.2, standoff 1, extent -4.635,3.45 -4.255,4.25
3D body: height 6.2, standoff 0, extent -6.35,-3.45 6.35,3.45

## TRS_MURATA_78601-1JC [mm] "MCD-04303"
height 6.35
pads (6):
  rect 1.6x1 smd mask+0.05: 1(-5.75,2.55) 2(-5.75,0) 3(-5.75,-2.54) 4(5.75,-2.54) 5(5.75,0) 6(5.75,2.54)
Top Overlay:
  circle w0.5: c2.15,1.5 r0.1
  circle w0.5: c-2.15,1.5 r0.1
  lines w0.12: -2.413,-2.032 -1.651,-2.032 ccw(c-1.651,-1.524) -1.651,-1.016 ccw(c-1.651,-0.508) -1.651,0 ccw(c-1.651,0.508) -1.651,1.016 ccw(c-1.651,1.524) -1.651,2.032 -2.413,2.032 ; -0.381,-2.032 -0.381,2.032 ; 0.381,-2.032 0.381,2.032 ; 2.413,-2.032 1.651,-2.032 cw(c1.651,-1.524) 1.651,-1.016 cw(c1.651,-0.508) 1.651,0 cw(c1.651,0.508) 1.651,1.016 cw(c1.651,1.524) 1.651,2.032 2.413,2.032 ; -4.75,-4.5 4.75,-4.5 4.75,4.5 -4.75,4.5 -4.75,-4.5
  text "1" at -5.879,2.611 h1.5
M14-Top Assembly:
  circle w0.5: c-2.15,1.525 r0.1
  circle w0.5: c2.15,1.525 r0.1
  lines w0.01: -4.75,-2.85 -6.35,-2.85 -6.35,-2.25 -4.75,-2.25 ; -4.75,-0.3 -6.35,-0.3 -6.35,0.3 -4.75,0.3 ; -4.75,2.275 -6.35,2.275 -6.35,2.875 -4.75,2.875 ; -2.413,-2.032 -1.651,-2.032 ccw(c-1.651,-1.524) -1.651,-1.016 ccw(c-1.651,-0.508) -1.651,0 ccw(c-1.651,0.508) -1.651,1.016 ccw(c-1.651,1.524) -1.651,2.032 -2.413,2.032 ; -0.381,-2.032 -0.381,2.032 ; 0.381,-2.032 0.381,2.032 ; 2.413,-2.032 1.651,-2.032 cw(c1.651,-1.524) 1.651,-1.016 cw(c1.651,-0.508) 1.651,0 cw(c1.651,0.508) 1.651,1.016 cw(c1.651,1.524) 1.651,2.032 2.413,2.032 ; 4.75,-2.85 6.35,-2.85 6.35,-2.25 4.75,-2.25 ; 4.75,-0.3 6.35,-0.3 6.35,0.3 4.75,0.3 ; 4.75,2.275 6.35,2.275 6.35,2.875 4.75,2.875 ; -4.75,-4.5 -4.75,4.5 4.75,4.5 4.75,-4.5 -4.75,-4.5
  text "4" at 5.242,-3.03 h1.5
  text "6" at 5.232,2.101 h1.5
  text "3" at -5.914,-3.024 h1.5
  text "1" at -5.877,2.143 h1.5
  text "'.Designator'" at -2,-0.5 h0.75
M16-Top Courtyard:
  lines w0.01: -6.7,-4.75 -6.7,4.75 6.7,4.75 6.7,-4.75 -6.7,-4.75
3D body "786J_MUR.step": height 6.66, standoff 0, extent -6.35,-4.496 6.35,4.496

## TRS_PULSE_H2019NL [mm]
height 5.97
pads (16):
  rect 0.64x1.4 smd mask+0.05: 1(-4.445,-4.51) 2(-3.175,-4.51) 3(-1.905,-4.51) 4(-0.635,-4.51) 5(0.635,-4.51) 6(1.905,-4.51) 7(3.175,-4.51) 8(4.445,-4.51) 9(4.445,4.51) 10(3.175,4.51) 11(1.905,4.51) 12(0.635,4.51) 13(-0.635,4.51) 14(-1.905,4.51) 15(-3.175,4.51) 16(-4.445,4.51)
Top Overlay:
  circle w0.12: c-4.445,-2.75 r0.45
  lines w0.12: -4.699,-3.7 -4.699,-3.55 ; -4.699,3.55 -4.699,3.7 ; -4.191,-3.7 -4.191,-3.55 ; -4.191,3.55 -4.191,3.7 ; -3.429,-3.7 -3.429,-3.55 ; -3.429,3.55 -3.429,3.7 ; -2.921,-3.7 -2.921,-3.55 ; -2.921,3.55 -2.921,3.7 ; -2.159,-3.7 -2.159,-3.55 ; -2.159,3.55 -2.159,3.7 ; -1.651,-3.7 -1.651,-3.55 ; -1.651,3.55 -1.651,3.7 ; -0.889,-3.7 -0.889,-3.55 ; -0.889,3.55 -0.889,3.7 ; -0.381,-3.7 -0.381,-3.55 ; -0.381,3.55 -0.381,3.7 ; 0.381,-3.7 0.381,-3.55 ; 0.381,3.55 0.381,3.7 ; 0.889,-3.7 0.889,-3.55 ; 0.889,3.55 0.889,3.7 ; 1.651,-3.7 1.651,-3.55 ; 1.651,3.55 1.651,3.7 ; 2.159,-3.7 2.159,-3.55 ; 2.159,3.55 2.159,3.7 ; 2.921,-3.7 2.921,-3.55 ; 2.921,3.55 2.921,3.7 ; 3.429,-3.7 3.429,-3.55 ; 3.429,3.55 3.429,3.7 ; 4.191,-3.7 4.191,-3.55 ; 4.191,3.55 4.191,3.7 ; 4.699,-3.7 4.699,-3.55 ; 4.699,3.55 4.699,3.7 ; -6.35,-3.425 ccw(c-6.225,-3.425) -6.225,-3.55 6.225,-3.55 ccw(c6.225,-3.425) 6.35,-3.425 6.35,3.425 ccw(c6.225,3.425) 6.225,3.55 -6.225,3.55 ccw(c-6.225,3.425) -6.35,3.425 -6.35,-3.425 ; -6.225,-3.3 ccw(c-6.1,-3.3) -6.1,-3.425 6.1,-3.425 ccw(c6.1,-3.3) 6.225,-3.3 6.225,3.3 ccw(c6.1,3.3) 6.1,3.425 -6.1,3.425 ccw(c-6.1,3.3) -6.225,3.3 -6.225,-3.3
  text "16" at -6.275,3.875 h1.5
  text "9" at 5,3.9 h1.5
  text "8" at 5,-4.825 h1.5
  text "1" at -5.35,-4.85 h1.5
M14-Top Assembly:
  circle w0.01: c-4.445,-2.75 r0.45
  lines w0.01: -4.699,-3.85 -4.191,-3.85 ; -4.699,-3.55 -4.699,-4.7 -4.191,-4.7 -4.191,-3.55 ; -4.699,3.55 -4.699,4.7 -4.191,4.7 -4.191,3.55 ; -4.699,3.85 -4.191,3.85 ; -3.429,-3.85 -2.921,-3.85 ; -3.429,-3.55 -3.429,-4.7 -2.921,-4.7 -2.921,-3.55 ; -3.429,3.55 -3.429,4.7 -2.921,4.7 -2.921,3.55 ; -3.429,3.85 -2.921,3.85 ; -2.159,-3.85 -1.651,-3.85 ; -2.159,-3.55 -2.159,-4.7 -1.651,-4.7 -1.651,-3.55 ; -2.159,3.55 -2.159,4.7 -1.651,4.7 -1.651,3.55 ; -2.159,3.85 -1.651,3.85 ; -0.889,-3.85 -0.381,-3.85 ; -0.889,-3.55 -0.889,-4.7 -0.381,-4.7 -0.381,-3.55 ; -0.889,3.55 -0.889,4.7 -0.381,4.7 -0.381,3.55 ; -0.889,3.85 -0.381,3.85 ; 0.381,-3.85 0.889,-3.85 ; 0.381,-3.55 0.381,-4.7 0.889,-4.7 0.889,-3.55 ; 0.381,3.55 0.381,4.7 0.889,4.7 0.889,3.55 ; 0.381,3.85 0.889,3.85 ; 1.651,-3.85 2.159,-3.85 ; 1.651,-3.55 1.651,-4.7 2.159,-4.7 2.159,-3.55 ; 1.651,3.55 1.651,4.7 2.159,4.7 2.159,3.55 ; 1.651,3.85 2.159,3.85 ; 2.921,-3.85 3.429,-3.85 ; 2.921,-3.55 2.921,-4.7 3.429,-4.7 3.429,-3.55 ; 2.921,3.55 2.921,4.7 3.429,4.7 3.429,3.55 ; 2.921,3.85 3.429,3.85 ; 4.191,-3.85 4.699,-3.85 ; 4.191,-3.55 4.191,-4.7 4.699,-4.7 4.699,-3.55 ; 4.191,3.55 4.191,4.7 4.699,4.7 4.699,3.55 ; 4.191,3.85 4.699,3.85 ; -6.35,-3.425 ccw(c-6.225,-3.425) -6.225,-3.55 6.225,-3.55 ccw(c6.225,-3.425) 6.35,-3.425 6.35,3.425 ccw(c6.225,3.425) 6.225,3.55 -6.225,3.55 ccw(c-6.225,3.425) -6.35,3.425 -6.35,-3.425 ; -6.225,-3.3 ccw(c-6.1,-3.3) -6.1,-3.425 6.1,-3.425 ccw(c6.1,-3.3) 6.225,-3.3 6.225,3.3 ccw(c6.1,3.3) 6.1,3.425 -6.1,3.425 ccw(c-6.1,3.3) -6.225,3.3 -6.225,-3.3
  text "16" at -4.975,3.89 h1.2
  text "9" at 4.195,3.88 h1.2
  text "8" at 4.195,-4.675 h1.2
  text "1" at -4.615,-4.68 h1.2
  text "'.Designator'" at -2,-0.5 h0.75
M16-Top Courtyard:
  lines w0.01: -6.55,-5.375 -6.15,-5.375 6.55,-5.375 6.55,-4.925 6.55,5.375 -4.775,5.375 -6.55,5.375 -6.55,3.3 -6.55,-5.375
3D body: height 0.25, standoff 0, extent -2.159,3.85 -1.651,4.7
3D body: height 1.25, standoff 0.25, extent -2.159,3.85 -1.651,4.15
3D body: height 1.5, standoff 1.25, extent -2.159,3.55 -1.651,4.15
3D body: height 0.25, standoff 0, extent -3.429,3.85 -2.921,4.7
3D body: height 1.25, standoff 0.25, extent -3.429,3.85 -2.921,4.15
3D body: height 1.5, standoff 1.25, extent -3.429,3.55 -2.921,4.15
3D body: height 1.5, standoff 1.25, extent -4.699,3.55 -4.191,4.15
3D body: height 1.25, standoff 0.25, extent -4.699,3.85 -4.191,4.15
3D body: height 0.25, standoff 0, extent -4.699,3.85 -4.191,4.7
3D body: height 1.5, standoff 1.25, extent -0.889,3.55 -0.381,4.15
3D body: height 1.25, standoff 0.25, extent -0.889,3.85 -0.381,4.15
3D body: height 0.25, standoff 0, extent -0.889,3.85 -0.381,4.7
3D body: height 1.5, standoff 1.25, extent 0.381,3.55 0.889,4.15
3D body: height 1.25, standoff 0.25, extent 0.381,3.85 0.889,4.15
3D body: height 0.25, standoff 0, extent 0.381,3.85 0.889,4.7
3D body: height 1.5, standoff 1.25, extent 1.651,3.55 2.159,4.15
3D body: height 1.25, standoff 0.25, extent 1.651,3.85 2.159,4.15
3D body: height 0.25, standoff 0, extent 1.651,3.85 2.159,4.7
3D body: height 1.5, standoff 1.25, extent 2.921,3.55 3.429,4.15
3D body: height 1.25, standoff 0.25, extent 2.921,3.85 3.429,4.15
3D body: height 0.25, standoff 0, extent 2.921,3.85 3.429,4.7
3D body: height 1.5, standoff 1.25, extent 4.191,3.55 4.699,4.15
3D body: height 1.25, standoff 0.25, extent 4.191,3.85 4.699,4.15
3D body: height 0.25, standoff 0, extent 4.191,3.85 4.699,4.7
3D body: height 1.5, standoff 1.25, extent 4.191,-4.15 4.699,-3.55
3D body: height 1.25, standoff 0.25, extent 4.191,-4.15 4.699,-3.85
3D body: height 0.25, standoff 0, extent 4.191,-4.7 4.699,-3.85
3D body: height 1.5, standoff 1.25, extent 2.921,-4.15 3.429,-3.55
3D body: height 1.25, standoff 0.25, extent 2.921,-4.15 3.429,-3.85
3D body: height 0.25, standoff 0, extent 2.921,-4.7 3.429,-3.85
3D body: height 1.5, standoff 1.25, extent 1.651,-4.15 2.159,-3.55
3D body: height 1.25, standoff 0.25, extent 1.651,-4.15 2.159,-3.85
3D body: height 0.25, standoff 0, extent 1.651,-4.7 2.159,-3.85
3D body: height 1.5, standoff 1.25, extent 0.381,-4.15 0.889,-3.55
3D body: height 1.25, standoff 0.25, extent 0.381,-4.15 0.889,-3.85
3D body: height 0.25, standoff 0, extent 0.381,-4.7 0.889,-3.85
3D body: height 1.5, standoff 1.25, extent -0.889,-4.15 -0.381,-3.55
3D body: height 1.25, standoff 0.25, extent -0.889,-4.15 -0.381,-3.85
3D body: height 0.25, standoff 0, extent -0.889,-4.7 -0.381,-3.85
3D body: height 1.5, standoff 1.25, extent -2.159,-4.15 -1.651,-3.55
3D body: height 1.25, standoff 0.25, extent -2.159,-4.15 -1.651,-3.85
3D body: height 0.25, standoff 0, extent -2.159,-4.7 -1.651,-3.85
3D body: height 1.5, standoff 1.25, extent -3.429,-4.15 -2.921,-3.55
3D body: height 1.25, standoff 0.25, extent -3.429,-4.15 -2.921,-3.85
3D body: height 0.25, standoff 0, extent -3.429,-4.7 -2.921,-3.85
3D body: height 1.5, standoff 1.25, extent -4.699,-4.15 -4.191,-3.55
3D body: height 1.25, standoff 0.25, extent -4.699,-4.15 -4.191,-3.85
3D body: height 0.25, standoff 0, extent -4.699,-4.7 -4.191,-3.85
3D body: height 0.75, standoff 0.25, extent -6.35,-3.55 -5.85,3.55
3D body: height 0.75, standoff 0.25, extent 5.85,-3.55 6.35,3.55
3D body: height 5.97, standoff 0.75, extent -6.35,-3.55 6.35,3.55
3D body: height 5.98, standoff 5.97, extent -4.896,-3.199 -4,-2.301

## TRS_PULSE_HU4006NL_P1 [mm] "MCD-03675"
height 6
pads (24):
  rect 0.64x1.775 smd mask+0.05: 1(-5.5,-7.113) 2(-4.5,-7.113) 3(-3.5,-7.113) 4(-2.5,-7.113) 5(-1.5,-7.113) 6(-0.5,-7.113) 7(0.5,-7.113) 8(1.5,-7.113) 9(2.5,-7.113) 10(3.5,-7.113) 11(4.5,-7.113) 12(5.5,-7.113) 13(5.5,7.113) 14(4.5,7.113) 15(3.5,7.113) 16(2.5,7.113) 17(1.5,7.113) 18(0.5,7.113) 19(-0.5,7.113) 20(-1.5,7.113) 21(-2.5,7.113) 22(-3.5,7.113) 23(-4.5,7.113) 24(-5.5,7.113)
Top Overlay:
  circle w0.12: c-5.5,-4 r0.5
  lines w0.12: -6.9,-5.3 6.9,-5.3 ; -6.9,5.3 6.9,5.3 ; -6,-6.1 -6.9,-6.1 -6.9,6.1 -6,6.1 ; -6,-4.009 -5.009,-4.009 ccw(c-5.009,-4) -5,-4 ; -5.507,-4.5 ccw(c-5.507,-4.493) -5.5,-4.493 -5.5,-3.5 ; 6,-6.1 6.9,-6.1 6.9,6.1 6,6.1 ; -6.6,-4.7 ccw(c-6.3,-4.7) -6.3,-5 6.3,-5 ccw(c6.3,-4.7) 6.6,-4.7 6.6,0 6.6,4.7 ccw(c6.3,4.7) 6.3,5 -6.3,5 ccw(c-6.3,4.7) -6.6,4.7 -6.6,0 -6.6,-4.7
  text "1" at -6.6,-7.5 h1.5
M14-Top Assembly:
  circle w0.01: c-5.5,-4 r0.5
  lines w0.01: -6.9,-5.3 6.9,-5.3 ; -6.9,5.3 6.9,5.3 ; -6,-4.009 -5.009,-4.009 ccw(c-5.009,-4) -5,-4 ; -5.7,-6.1 -5.7,-7.6 -5.3,-7.6 -5.3,-6.1 ; -5.7,6.1 -5.7,7.6 -5.3,7.6 -5.3,6.1 ; -5.507,-4.5 ccw(c-5.507,-4.493) -5.5,-4.493 -5.5,-3.5 ; -4.7,-6.1 -4.7,-7.6 -4.3,-7.6 -4.3,-6.1 ; -4.7,6.1 -4.7,7.6 -4.3,7.6 -4.3,6.1 ; -3.7,-6.1 -3.7,-7.6 -3.3,-7.6 -3.3,-6.1 ; -3.7,6.1 -3.7,7.6 -3.3,7.6 -3.3,6.1 ; -2.7,-6.1 -2.7,-7.6 -2.3,-7.6 -2.3,-6.1 ; -2.7,6.1 -2.7,7.6 -2.3,7.6 -2.3,6.1 ; -1.7,-6.1 -1.7,-7.6 -1.3,-7.6 -1.3,-6.1 ; -1.7,6.1 -1.7,7.6 -1.3,7.6 -1.3,6.1 ; -0.7,-6.1 -0.7,-7.6 -0.3,-7.6 -0.3,-6.1 ; -0.7,6.1 -0.7,7.6 -0.3,7.6 -0.3,6.1 ; 0.3,-6.1 0.3,-7.6 0.7,-7.6 0.7,-6.1 ; 0.3,6.1 0.3,7.6 0.7,7.6 0.7,6.1 ; 1.3,-6.1 1.3,-7.6 1.7,-7.6 1.7,-6.1 ; 1.3,6.1 1.3,7.6 1.7,7.6 1.7,6.1 ; 2.3,-6.1 2.3,-7.6 2.7,-7.6 2.7,-6.1 ; 2.3,6.1 2.3,7.6 2.7,7.6 2.7,6.1 ; 3.3,-6.1 3.3,-7.6 3.7,-7.6 3.7,-6.1 ; 3.3,6.1 3.3,7.6 3.7,7.6 3.7,6.1 ; 4.3,-6.1 4.3,-7.6 4.7,-7.6 4.7,-6.1 ; 4.3,6.1 4.3,7.6 4.7,7.6 4.7,6.1 ; 5.3,-6.1 5.3,-7.6 5.7,-7.6 5.7,-6.1 ; 5.3,6.1 5.3,7.6 5.7,7.6 5.7,6.1 ; -6.9,-6.1 -6.9,6.1 6.9,6.1 6.9,-6.1 -6.9,-6.1 ; -6.6,-4.7 ccw(c-6.3,-4.7) -6.3,-5 6.3,-5 ccw(c6.3,-4.7) 6.6,-4.7 6.6,0 6.6,4.7 ccw(c6.3,4.7) 6.3,5 -6.3,5 ccw(c-6.3,4.7) -6.6,4.7 -6.6,0 -6.6,-4.7
  text "24" at -6.195,6.5 h1.5
  text "13" at 4.857,6.517 h1.5
  text "12" at 4.862,-7.464 h1.5
  text "1" at -5.677,-7.464 h1.5
  text "'.Designator'" at -2,-0.5 h0.75
M16-Top Courtyard:
  lines w0.01: -7.2,-8.2 7.2,-8.2 7.2,8.2 -7.2,8.2 -7.2,-8.2
3D body: height 1.6, standoff 0, extent -0.7,-6.9 -0.3,-6.8
3D body: height 1.6, standoff 1.4, extent -0.7,-6.85 -0.3,-6.1
3D body: height 0.2, standoff 0, extent -0.7,-7.6 -0.3,-6.85
3D body: height 1.6, standoff 0, extent -1.7,-6.9 -1.3,-6.8
3D body: height 1.6, standoff 1.4, extent -1.7,-6.85 -1.3,-6.1
3D body: height 0.2, standoff 0, extent -1.7,-7.6 -1.3,-6.85
3D body: height 1.6, standoff 0, extent -2.7,-6.9 -2.3,-6.8
3D body: height 1.6, standoff 1.4, extent -2.7,-6.85 -2.3,-6.1
3D body: height 0.2, standoff 0, extent -2.7,-7.6 -2.3,-6.85
3D body: height 1.6, standoff 1.4, extent -3.7,-6.85 -3.3,-6.1
3D body: height 0.2, standoff 0, extent -3.7,-7.6 -3.3,-6.85
3D body: height 1.6, standoff 0, extent -4.7,-6.9 -4.3,-6.8
3D body: height 1.6, standoff 1.4, extent -4.7,-6.85 -4.3,-6.1
3D body: height 0.2, standoff 0, extent -4.7,-7.6 -4.3,-6.85
3D body: height 1.6, standoff 0, extent -5.7,-6.9 -5.3,-6.8
3D body: height 1.6, standoff 1.4, extent -5.7,-6.85 -5.3,-6.1
3D body: height 0.2, standoff 0, extent -5.7,-7.6 -5.3,-6.85
3D body: height 1.6, standoff 0, extent 5.3,-6.9 5.7,-6.8
3D body: height 0.2, standoff 0, extent 5.3,-7.6 5.7,-6.85
3D body: height 1.6, standoff 0, extent 4.3,-6.9 4.7,-6.8
3D body: height 0.2, standoff 0, extent 4.3,-7.6 4.7,-6.85
3D body: height 1.6, standoff 0, extent 3.3,-6.9 3.7,-6.8
3D body: height 0.2, standoff 0, extent 3.3,-7.6 3.7,-6.85
3D body: height 1.6, standoff 0, extent 2.3,-6.9 2.7,-6.8
3D body: height 0.2, standoff 0, extent 2.3,-7.6 2.7,-6.85
3D body: height 1.6, standoff 0, extent -3.7,-6.9 -3.3,-6.8
3D body: height 1.6, standoff 1.4, extent 5.3,-6.85 5.7,-6.1
3D body: height 1.6, standoff 1.4, extent 4.3,-6.85 4.7,-6.1
3D body: height 1.6, standoff 0, extent 1.3,6.8 1.7,6.9
3D body: height 1.6, standoff 1.4, extent 1.3,6.1 1.7,6.85
3D body: height 0.2, standoff 0, extent 1.3,6.85 1.7,7.6
3D body: height 1.6, standoff 0, extent -2.7,6.8 -2.3,6.9
3D body: height 1.6, standoff 1.4, extent -2.7,6.1 -2.3,6.85
3D body: height 0.2, standoff 0, extent -2.7,6.85 -2.3,7.6
3D body: height 1.6, standoff 0, extent -1.7,6.8 -1.3,6.9
3D body: height 1.6, standoff 1.4, extent -1.7,6.1 -1.3,6.85
3D body: height 0.2, standoff 0, extent -1.7,6.85 -1.3,7.6
3D body: height 1.6, standoff 1.4, extent -5.7,6.1 -5.3,6.85
3D body: height 1.6, standoff 0, extent -5.7,6.8 -5.3,6.9
3D body: height 0.2, standoff 0, extent -5.7,6.85 -5.3,7.6
3D body: height 1.6, standoff 0, extent -4.7,6.8 -4.3,6.9
3D body: height 1.6, standoff 1.4, extent -4.7,6.1 -4.3,6.85
3D body: height 0.2, standoff 0, extent -4.7,6.85 -4.3,7.6
3D body: height 1.6, standoff 0, extent -3.7,6.8 -3.3,6.9
3D body: height 1.6, standoff 1.4, extent -3.7,6.1 -3.3,6.85
3D body: height 0.2, standoff 0, extent -3.7,6.85 -3.3,7.6
3D body: height 1.6, standoff 0, extent -0.7,6.8 -0.3,6.9
3D body: height 1.6, standoff 1.4, extent -0.7,6.1 -0.3,6.85
3D body: height 0.2, standoff 0, extent -0.7,6.85 -0.3,7.6
3D body: height 1.6, standoff 0, extent 0.3,6.8 0.7,6.9
3D body: height 1.6, standoff 1.4, extent 0.3,6.1 0.7,6.85
3D body: height 0.2, standoff 0, extent 0.3,6.85 0.7,7.6
3D body: height 1.6, standoff 0, extent 4.3,6.8 4.7,6.9
3D body: height 1.6, standoff 1.4, extent 4.3,6.1 4.7,6.85
3D body: height 0.2, standoff 0, extent 4.3,6.85 4.7,7.6
3D body: height 1.6, standoff 0, extent 5.3,6.8 5.7,6.9
3D body: height 1.6, standoff 1.4, extent 5.3,6.1 5.7,6.85
3D body: height 0.2, standoff 0, extent 5.3,6.85 5.7,7.6
3D body: height 1.6, standoff 0, extent 2.3,6.8 2.7,6.9
3D body: height 1.6, standoff 1.4, extent 2.3,6.1 2.7,6.85
3D body: height 0.2, standoff 0, extent 2.3,6.85 2.7,7.6
3D body: height 1.6, standoff 0, extent 3.3,6.8 3.7,6.9
3D body: height 1.6, standoff 1.4, extent 3.3,6.1 3.7,6.85
3D body: height 0.2, standoff 0, extent 3.3,6.85 3.7,7.6
3D body: height 1.6, standoff 0, extent 1.3,-6.9 1.7,-6.8
3D body: height 1.6, standoff 1.4, extent 1.3,-6.85 1.7,-6.1
3D body: height 0.2, standoff 0, extent 1.3,-7.6 1.7,-6.85
3D body: height 1.6, standoff 0, extent 0.3,-6.9 0.7,-6.8
3D body: height 1.6, standoff 1.4, extent 0.3,-6.85 0.7,-6.1
3D body: height 0.2, standoff 0, extent 0.3,-7.6 0.7,-6.85
3D body: height 1.6, standoff 1.4, extent 3.3,-6.85 3.7,-6.1
3D body: height 1.6, standoff 1.4, extent 2.3,-6.85 2.7,-6.1
3D body: height 2, standoff 0, extent -6.914,-6.1 6.9,6.1
3D body: height 6, standoff 2, extent -6.9,-5.3 6.9,5.35
3D body: height 6.01, standoff 6, extent -6,-4.509 -5,-3.509

## TRS_PULSE_PE-68386NL [mm] "MCD-04178"
height 2.49
pads (4):
  rect 1.15x2 smd mask+0.05: 1(-3.365,2.54) 3(-3.365,-2.54) 4(3.365,-2.54) 6(3.365,2.54)
Top Overlay:
  lines w0.12: -3.365,-1.253 -3.365,1.248 ; -2.497,3.365 2.484,3.365 ; -2.484,-3.365 2.497,-3.365 ; 3.365,-1.248 3.365,1.253
  text "1" at -4.575,3.1 h1.5
M14-Top Assembly:
  circle w0.01: c-2.575,2.8 r0.246
  lines w0.01: -3.37,-3.017 -4.325,-3.017 -4.325,-2.063 -3.37,-2.063 ; -3.37,-0.477 -4.325,-0.477 -4.325,0.477 -3.37,0.477 ; -3.37,2.063 -4.325,2.063 -4.325,3.017 -3.37,3.017 ; 3.37,-3.017 4.325,-3.017 4.325,-2.063 3.37,-2.063 ; 3.37,-0.477 4.325,-0.477 4.325,0.477 3.37,0.477 ; 3.37,2.063 4.325,2.063 4.325,3.017 3.37,3.017 ; -3.365,-3.365 3.365,-3.365 3.365,3.365 -3.365,3.365 -3.365,-3.365
  text "6" at 3.55,2.125 h1.3
  text "4" at 3.525,-2.975 h1.3
  text "3" at -4.125,-2.95 h1.3
  text "1" at -4.05,2.15 h1.3
  text "'.Designator'" at -2,-0.5 h0.75
M16-Top Courtyard:
  lines w0.01: -4.525,-3.7 -4.525,3.7 4.525,3.7 4.525,-3.7 -4.525,-3.7
3D body "PE-68386NL.STEP": height 2.3, standoff -0.03, extent -4.325,-3.01 4.311,3.01

## TRS_TDK_B82804A0354A110 [mm] "MCD-03619"
height 5.4
pads (6):
  rect 1.2x1.5 smd mask+0.05: 1(-1.85,-3.65) 2(0,-3.65) 3(1.85,-3.65) 4(1.85,3.65) 5(0,3.65) 6(-1.85,3.65)
Top Overlay:
  circle w0.5: c1.5,-2.15 r0.1
  circle w0.5: c1.5,2.15 r0.1
  lines w0.12: -2.6,-3.05 -3.35,-3.05 -3.35,3.05 -2.6,3.05 ; -2.032,-2.413 -2.032,-1.651 cw(c-1.524,-1.651) -1.016,-1.651 cw(c-0.508,-1.651) 0,-1.651 cw(c0.508,-1.651) 1.016,-1.651 cw(c1.524,-1.651) 2.032,-1.651 2.032,-2.413 ; -2.032,-0.381 2.032,-0.381 ; -2.032,0.381 2.032,0.381 ; -2.032,2.413 -2.032,1.651 ccw(c-1.524,1.651) -1.016,1.651 ccw(c-0.508,1.651) 0,1.651 ccw(c0.508,1.651) 1.016,1.651 ccw(c1.524,1.651) 2.032,1.651 2.032,2.413 ; -1.1,-3.05 -0.75,-3.05 ; -1.1,3.05 -0.75,3.05 ; 0.75,-3.05 1.1,-3.05 ; 0.75,3.05 1.1,3.05 ; 2.6,-3.05 3.35,-3.05 3.35,3.05 2.6,3.05
  text "1" at -3.154,-4.264 h1.5
M14-Top Assembly:
  circle w0.5: c1.5,-2.15 r0.1
  circle w0.5: c1.5,2.15 r0.1
  lines w0.01: -2.15,-3.05 -2.15,-4.05 -1.55,-4.05 -1.55,-3.05 ; -2.15,3.05 -2.15,4.05 -1.55,4.05 -1.55,3.05 ; -2.032,-2.413 -2.032,-1.651 cw(c-1.524,-1.651) -1.016,-1.651 cw(c-0.508,-1.651) 0,-1.651 cw(c0.508,-1.651) 1.016,-1.651 cw(c1.524,-1.651) 2.032,-1.651 2.032,-2.413 ; -2.032,-0.381 2.032,-0.381 ; -2.032,0.381 2.032,0.381 ; -2.032,2.413 -2.032,1.651 ccw(c-1.524,1.651) -1.016,1.651 ccw(c-0.508,1.651) 0,1.651 ccw(c0.508,1.651) 1.016,1.651 ccw(c1.524,1.651) 2.032,1.651 2.032,2.413 ; -0.3,-3.05 -0.3,-4.05 0.3,-4.05 0.3,-3.05 ; -0.3,3.05 -0.3,4.05 0.3,4.05 0.3,3.05 ; 1.55,-3.05 1.55,-4.05 2.15,-4.05 2.15,-3.05 ; 1.55,3.05 1.55,4.05 2.15,4.05 2.15,3.05 ; -3.35,-3.05 -3.35,3.05 3.35,3.05 3.35,-3.05 -3.35,-3.05
  text "4" at 1.517,3.07 h1.5
  text "6" at -2.168,3.076 h1.5
  text "3" at 1.536,-4.024 h1.5
  text "1" at -2.077,-4.032 h1.5
  text "'.Designator'" at -2,-0.5 h0.75
M16-Top Courtyard:
  lines w0.01: -3.55,-4.55 -3.55,4.55 -2.5,4.55 3.55,4.55 3.55,-4.55 -3.55,-4.55
3D body "B82804A_EP5_MAX_public_TDK-PC.step": height 5.4, standoff 0, extent -3.35,-4.05 3.35,4.05

## TRS_WURTH_749251125 [mm] "MCD-01570"
height 5.33
pads (8):
  rect 1.6x1.2 smd mask+0.05: 1(-3.6,1.85) 2(-3.6,0) 3(-3.6,-1.85) 4(3.6,-1.85) 5(3.6,0) 6(3.6,1.85)
  rect 3x2.5 smd mask+0.05: 7(0,-2.6) 8(0,2.6)
Top Overlay:
  lines w0.12: -3,-2.575 -3,-3 -1.625,-3 ; -3,-1.125 -3,-0.725 ; -3,0.725 -3,1.125 ; -3,2.575 -3,3 -1.625,3 ; -1.625,-2.25 -2.25,-2.25 -2.25,2.25 -1.625,2.25 ; 1.625,-3 3,-3 3,-2.575 ; 1.625,-2.25 2.25,-2.25 2.25,2.25 1.625,2.25 ; 1.625,3 3,3 3,2.575 ; 3,-1.125 3,-0.725 ; 3,0.725 3,1.125
  text "7" at 1.625,-4.075 h1.5
  text "8" at 1.625,3.125 h1.5
  text "3" at -3.9,-3.55 h1.5
  text "1" at -3.75,2.575 h1.5
M14-Top Assembly:
  lines w0.01: -3,-2.375 -3.9,-2.375 -3.9,-1.325 -3,-1.325 ; -3,-0.525 -3.9,-0.525 -3.9,0.525 -3,0.525 ; -3,1.325 -3.9,1.325 -3.9,2.375 -3,2.375 ; -1.425,-3 -1.425,-3.6 1.425,-3.6 1.425,-3 ; -1.425,3 -1.425,3.6 1.425,3.6 1.425,3 ; 3,-2.375 3.9,-2.375 3.9,-1.325 3,-1.325 ; 3,-0.525 3.9,-0.525 3.9,0.525 3,0.525 ; 3,1.325 3.9,1.325 3.9,2.375 3,2.375 ; -3,-3 3,-3 3,3 -3,3 -3,-3 ; -2.25,-2.25 -2.25,2.25 2.25,2.25 2.25,-2.25 -2.25,-2.25
  text "8" at -0.275,2.7 h1.3
  text "6" at 3.175,1.45 h1.3
  text "5" at 3.175,-0.4 h1.3
  text "4" at 3.15,-2.275 h1.3
  text "7" at -0.275,-3.55 h1.3
  text "3" at -3.725,-2.275 h1.3
  text "2" at -3.725,-0.425 h1.3
  text "1" at -3.6,1.425 h1.3
  text "'.Designator'" at -2,-0.5 h0.75
M16-Top Courtyard:
  lines w0.01: -4.55,-4 -4.55,2.5 -4.55,4 4.55,4 4.55,3.7 4.55,-4 -4.55,-4
3D body "STEP-WE-CST-EE5-rev1.stp": height 5.33, standoff 0, extent -3.85,-3.45 3.85,3.45
3D body: height 5.33, standoff 0, extent -3,-3 3,3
